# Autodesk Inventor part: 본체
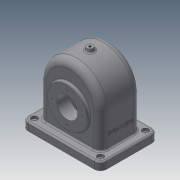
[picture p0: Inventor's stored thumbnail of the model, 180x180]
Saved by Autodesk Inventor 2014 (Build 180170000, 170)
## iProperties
Created: 2016-10
Part Number: 본체
Material: 일반
Document SubType Name: Modeling
Designer: 703-17
Density: 1 g/cm^3
Appearance: 기본값
Author: 703-17
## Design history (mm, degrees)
sketch "스케치2"
  geometry: L1 (-55, 75)-(55, 75); L2 (55, 75)-(55, -75); L3 (55, -75)-(-55, -75); L4 (-55, -75)-(-55, 75); L5 (-55, 75)-(55, -75); L6 (55, 75)-(-55, -75); 1 further point
  constraints: 12 end point, 2 midpoint, 2 parallel, 1 horizontal, 1 perpendicular
  dimensions: "d2" = 150 distance between parallel lines of L3 L1; "d3" = 110 distance between parallel lines of L2 L4
extrude "돌출1" new body sketch "스케치2" distance "d4" = 15; taper "d5" = 0 deg
fillet "모깎기1" dims "d6" = 12
sketch "스케치3"
  geometry: L1 (-38.5, -58)-(38.5, -58); L2 (38.5, -58)-(38.5, 58); L3 (38.5, 58)-(-38.5, 58); L4 (-38.5, 58)-(-38.5, -58); L5 (-38.5, -58)-(38.5, 58); L6 (38.5, -58)-(-38.5, 58); 3 further points
  constraints: 12 end point, 3 midpoint, 2 parallel, 1 coincident, 1 horizontal, 1 perpendicular
  dimensions: "d7" = 77 distance between parallel lines of L4 L2; "d57" = 116 distance between parallel lines of L1 L3
extrude "돌출2" join sketch "스케치3" distance "d10" = 65; taper "d11" = 0 deg
sketch "스케치4"
  geometry: L1 (-38.5, 58)-(-38.5, -58) reference; L2 (-38.5, 0)-(38.5, 0); L3 (38.5, 0)-(38.5, 58); L4 (38.5, 58)-(-38.5, 58); L5 (-38.5, 58)-(-38.5, 0); 1 further point
  constraints: 8 end point, 2 parallel, 1 horizontal, 1 midpoint, 1 perpendicular
revolve "회전1" sketch "스케치4" stored, may be unused: angle "d12" = 180 deg
sketch "스케치5"
  geometry: L1 (0, 0)-(-65, 0); L2 (15, 121)-(15, -5) reference; C1 r 31 at (-50, 58); A1 r 59.908 centre (-50, 58) between (-65, 116) and (-65, 0); 1 further point
  constraints: 2 centre point, 2 end point, 2 point on circle, 1 coincident
  dimensions: "d13" = 62 diameter of C1; "d86" = 65 distance from line of L2 A1.centre
extrude "돌출3" join sketch "스케치5" distance "d14" = 10; taper "d15" = 0 deg
sketch "스케치6"
  geometry: L1 (0, 0)-(0, 116); L2 (0, 0)-(65, 0); L3 (0, 116)-(65, 116); L4 (-15, -5)-(-15, 121) reference; C1 r 37.5 at (50, 58); A1 r 59.908 centre (50, 58) between (65, 0) and (65, 116); 1 further point
  constraints: 6 end point, 2 centre point, 2 point on circle, 1 coincident
  dimensions: "d16" = 75 diameter of C1; "d87" = 65 distance from line of L4 A1.centre
extrude "돌출4" join sketch "스케치6" distance "d17" = 5; taper "d18" = 0 deg
sketch "스케치8"
  geometry: L1 (-33.5, -52)-(33.5, -52); L2 (33.5, -52)-(33.5, 52); L3 (33.5, 52)-(-33.5, 52); L4 (-33.5, 52)-(-33.5, -52); L5 (-33.5, -52)-(33.5, 52); L6 (33.5, -52)-(-33.5, 52); L7 (-38.5, 58)-(38.5, 58) reference; L8 (38.5, -58)-(38.5, 58) reference; 1 further point
  constraints: 12 end point, 2 midpoint, 2 parallel, 1 horizontal, 1 perpendicular
  dimensions: "d19" = 6 distance between parallel lines of L7 L3; "d20" = 5 distance between parallel lines of L8 L2
extrude "돌출5" cut sketch "스케치8" distance "d21" = 80; taper "d22" = 0 deg
sketch "스케치9"
  geometry: L1 (-33.5, -52)-(-33.5, 52) reference; L2 (-33.5, 0)-(33.5, 0); L3 (33.5, 0)-(33.5, 52); L4 (33.5, 52)-(-33.5, 52); L5 (-33.5, 52)-(-33.5, 0); 1 further point
  constraints: 8 end point, 2 parallel, 1 horizontal, 1 midpoint, 1 perpendicular
revolve "회전2" sketch "스케치9" stored, may be unused: angle "d23" = 180 deg
sketch "스케치10"
  geometry: L1 (36.521, 107.282)-(19.5, 93); L2 (19.5, 93)-(19.5, 65); L3 (19.5, 65)-(36.521, 65); L4 (36.521, 65)-(36.521, 107.282); L5 (43.5, 27.5)-(43.5, 102.5) reference; L6 (43, 0)-(-43, 0) reference; 1 further point
  constraints: 8 end point, 2 perpendicular, 1 vertical
  dimensions: "d24" = 50 deg angle of L2 L1; "d25" = 24 distance between parallel lines of L5 L2; "d26" = 56 diameter of L1.end L3; "d88" = 65 distance between parallel lines of L6 L3
revolve "회전3" sketch "스케치10" stored, may be unused: angle "d27" = 180 deg
sketch "스케치12"
  geometry: C1 r 31 at (0, 0) reference; 1 further point
hole "구멍1" sketch "스케치12" at (0, 0) diameter "d28" = 40; stored, may be unused: countersink angle "d32" = 90 deg, drill point angle "d34" = 118 deg; dims "d29" = 6, "d30" = 4, "d31" = 2, "d33" = 8
sketch "스케치15"
  geometry: L1 (0, 144)-(6, 144); L2 (6, 144)-(7.825, 133.651); L3 (7.825, 133.651)-(0, 133.651); L4 (0, 133.651)-(0, 144); L5 (43, 0)-(-43, 0) reference; 3 further points
  constraints: 8 end point, 2 midpoint, 1 horizontal, 1 parallel, 1 perpendicular, 1 vertical alignment
  dimensions: "d37" = 100 deg angle of L2 L3; "d39" = 12 diameter of L1.end L4; "d40" = 144 distance between parallel lines of L1 L5
revolve "회전4" sketch "스케치15" stored, may be unused: angle "d41" = 180 deg
sketch "스케치16"
  geometry: C1 r 6 at (0, 0) reference
hole "구멍2" sketch "스케치16" at (0, 0) diameter "d42" = 4.459; stored, may be unused: countersink angle "d46" = 90 deg, drill point angle "d48" = 118 deg; dims "d43" = 6, "d44" = 4, "d45" = 2, "d47" = 8
sketch "스케치17"
  geometry: A1 r 12 centre (-43, 63) between (-43, 75) and (-55, 63) reference; A2 r 12 centre (-43, -63) between (-55, -63) and (-43, -75) reference; A3 r 12 centre (43, -63) between (43, -75) and (55, -63) reference; A4 r 12 centre (43, 63) between (55, 63) and (43, 75) reference; 1 further point
hole "구멍3" sketch "스케치17" at (-43, -63), (-43, 63), (43, 63), (43, -63) diameter "d49" = 5; stored, may be unused: countersink angle "d53" = 90 deg, drill point angle "d55" = 118 deg; dims "d50" = 5, "d51" = 12, "d52" = 5, "d54" = 8
fillet "모깎기3" dims "d58" = 13
fillet "모깎기4" dims "d59" = 3
fillet "모깎기5" dims "d60" = 8
fillet "모깎기6" dims "d61" = 3
sketch "스케치18" dims "d62" = 58
  geometry: C1 r 37.5 at (0, 0) reference; 3 further points
  constraints: 1 coincident, 1 horizontal alignment, 2 other
hole "구멍4" sketch "스케치18" at (29, 0) diameter "d63" = 2.459; stored, may be unused: countersink angle "d67" = 90 deg, drill point angle "d69" = 118 deg; dims "d64" = 6, "d65" = 12, "d66" = 5, "d68" = 8
sketch "스케치19" dims "d73" = 52
  geometry: C1 r 31 at (0, 0) reference; 3 further points
  constraints: 1 coincident, 1 horizontal alignment, 2 other
hole "구멍5" sketch "스케치19" at (-26, 0) diameter "d74" = 2.459; stored, may be unused: countersink angle "d78" = 90 deg, drill point angle "d80" = 118 deg; dims "d75" = 6, "d76" = 12, "d77" = 5, "d79" = 8
sketch "스케치20" dims "d2" = 150, "d3" = 110
  geometry: L1 (68.5, -80)-(-17.5, -80) reference; L2 (-13, 0)-(-13, -62) reference; 2 further points
  constraints: 1 other
  dimensions: "d84" = 40 distance from line of L1 point (25.5, -40); "d85" = 38.5 distance from line of point (25.5, -40) L2
feature "엠보싱1" sketch "스케치20" dims "d2" = 150, "d3" = 110, "d89" = 0.5, "d90" = 0
node "솔리드1"
pattern_circular "원형 패턴1" dims angle "d71" = 360 deg
pattern_circular "원형 패턴2" dims angle "d82" = 360 deg
